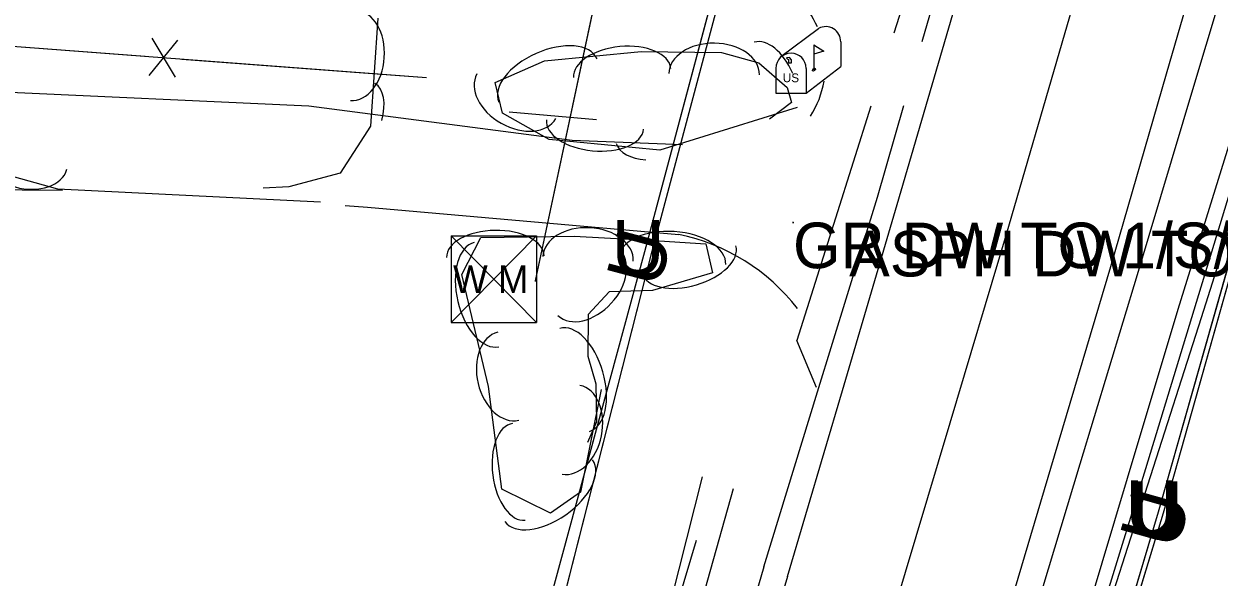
# Model space of a CAD drawing. Extents: x 954793 to 988390, y 1867850 to 1924428.
# Drawn here: x 961177.2 to 961308.1, y 1906549.5 to 1906610.1 of the extents above; entities that cross this region are included whole.
import ezdxf

# ---------------------------------------------------------------- set-up
doc = ezdxf.new("R2010")
doc.units = 0
for name, color, linetype in [('Default', 7, 'Continuous'), ('S_DITCHLINE', 7, 'Continuous'), ('S_DRIVEWAY', 7, 'Continuous'), ('S_EDGE_PAVEMENT', 7, 'Continuous'), ('S_FENCE', 7, 'Continuous'), ('S_FIBER_OPTIC_CABLE', 7, 'Continuous'), ('S_MAILBOX', 7, 'Continuous'), ('S_MSC_PT_SYM', 7, 'Continuous'), ('S_PAVEMENT_CROWN', 7, 'Continuous'), ('S_SHOULDER', 7, 'Continuous'), ('S_STREAM', 7, 'Continuous'), ('S_SURVEY_TEXT_ANNOT', 7, 'Continuous'), ('S_TREE', 7, 'Continuous'), ('S_UNDERGROUND_CABLE', 7, 'Continuous'), ('S_UTL_PT_SYM', 7, 'Continuous'), ('S_WATER_UTILITIES', 7, 'Continuous')]:
    doc.layers.add(name, color=color, linetype=linetype)

msp = doc.modelspace()

# ---------------------------------------------------------------- linework, layer by layer
at = {"layer": 'S_DITCHLINE'}
for points in [[(961281.36, 1906504.67), (961286.92, 1906523.21), (961292.47, 1906541.76), (961298.03, 1906560.31), (961303.59, 1906578.85), (961308.97, 1906596.26), (961314.35, 1906613.67), (961319.73, 1906631.07), (961325.12, 1906648.48), (961330.22, 1906665.83), (961335.33, 1906683.19), (961340.43, 1906700.54), (961345.54, 1906717.9), (961348.74, 1906734.13), (961351.94, 1906750.37), (961355.14, 1906766.6), (961358.34, 1906782.84), (961361.82, 1906806.99), (961365.31, 1906831.14), (961367.48, 1906844.45), (961369.65, 1906857.75), (961371.81, 1906871.05), (961373.98, 1906884.36), (961378.38, 1906886.56)], [(961282.64, 1906504.52), (961288.51, 1906522.87), (961294.39, 1906541.22), (961300.26, 1906559.57), (961306.13, 1906577.92), (961311.67, 1906595.41), (961317.2, 1906612.89), (961322.74, 1906630.37), (961328.27, 1906647.86), (961333.11, 1906665.38), (961337.96, 1906682.91), (961342.8, 1906700.43), (961347.64, 1906717.96), (961351.32, 1906734.05), (961354.99, 1906750.15), (961358.67, 1906766.25), (961362.35, 1906782.35), (961365.3, 1906806.52), (961368.26, 1906830.68), (961371.46, 1906851.53), (961374.67, 1906872.38)], [(961220.79, 1906448.63), (961225.92, 1906466.47), (961231.04, 1906484.31), (961236.17, 1906502.15), (961241.29, 1906519.99), (961246.4, 1906540.22), (961251.51, 1906560.45)], [(961222.13, 1906448.62), (961227.51, 1906466.25), (961232.88, 1906483.88), (961238.26, 1906501.51), (961243.64, 1906519.13), (961249.27, 1906539.15), (961254.9, 1906559.16)]]:
    msp.add_lwpolyline(points, dxfattribs=at)
at = {"layer": 'S_DRIVEWAY'}
for points in [[(961278.77, 1906629.04), (961274.53, 1906615.64), (961272.46, 1906609.07)], [(961249.3, 1906596.84), (961237.24, 1906597.32), (961208.39, 1906601.1), (961173.28, 1906602.68), (961146.27, 1906602.71), (961138.49, 1906603.17)], [(961269.93, 1906601.07), (961266.06, 1906588.82), (961261.82, 1906575.41)], [(961141.93, 1906588.1), (961163.73, 1906592.02), (961181.4, 1906591.86)], [(961212.38, 1906590.19), (961214.81, 1906590.01), (961248.89, 1906587.03)], [(961263.99, 1906570.24), (961261.82, 1906575.41)]]:
    msp.add_lwpolyline(points, dxfattribs=at)
for centre, major_axis, ratio, start_param, end_param in [((961254.62, 1906605.58), (-0.07, 10.35), 0.998866, 5.12227, 5.484198), ((961254.62, 1906605.58), (-0.07, 10.35), 0.998866, 4.136681, 4.533449), ((961244.25, 1906565.09), (-16.71, 14.97), 0.999649, 4.536311, 5.234086)]:
    msp.add_ellipse(centre, major_axis=major_axis, ratio=ratio, start_param=start_param, end_param=end_param, dxfattribs=at)
at = {"layer": 'S_EDGE_PAVEMENT'}
for points in [[(961260.82, 1906549.54), (961266.81, 1906569.92), (961272.8, 1906590.3), (961278.91, 1906611.17), (961285.01, 1906632.04), (961290.97, 1906653.41), (961296.93, 1906674.79), (961302.13, 1906694.47), (961307.33, 1906714.15), (961311.92, 1906734.12), (961316.51, 1906754.09), (961320.15, 1906774.24), (961323.79, 1906794.39), (961326.05, 1906811.77), (961328.31, 1906829.15), (961329.62, 1906844.79), (961330.93, 1906860.42), (961331.31, 1906876.09), (961331.42, 1906880.69)], [(961283.86, 1906541.96), (961290.03, 1906562.74), (961296.2, 1906583.52), (961302.31, 1906604.64), (961308.42, 1906625.77), (961314.44, 1906646.9), (961320.46, 1906668.02), (961325.86, 1906688.27), (961331.25, 1906708.51), (961336.02, 1906729.15), (961340.8, 1906749.78), (961344.46, 1906769.29), (961347.73, 1906786.69)], [(961260.82, 1906549.54), (961254.71, 1906529.11), (961248.6, 1906508.69)]]:
    msp.add_lwpolyline(points, dxfattribs=at)
at = {"layer": 'S_FENCE'}
for p, q in [((961191.2, 1906608.55), (961193.75, 1906604.25)), ((961190.89, 1906604.46), (961194.06, 1906608.33))]:
    msp.add_line(p, q, dxfattribs=at)
for points in [[(961170.56, 1906608.06), (961190.48, 1906606.55)], [(961170.56, 1906608.06), (961221.27, 1906604.22)], [(961194.47, 1906606.24), (961214.39, 1906604.74)], [(961214.39, 1906604.74), (961221.27, 1906604.22)], [(961230.32, 1906600.47), (961239.89, 1906599.62)]]:
    msp.add_lwpolyline(points, dxfattribs=at)
at = {"layer": 'S_FIBER_OPTIC_CABLE'}
for p, q in [((961245.94, 1906585.05), (961263.31, 1906650.29)), ((961231.67, 1906528.87), (961245.94, 1906585.05))]:
    msp.add_line(p, q, dxfattribs=at)
msp.add_lwpolyline([(961285.83, 1906512.94), (961239.76, 1906525.04), (961231.67, 1906528.87), (961245.94, 1906585.05), (961263.31, 1906650.29), (961274.95, 1906713.95), (961277.65, 1906742.92), (961276.99, 1906766.38), (961281.46, 1906820.82), (961281.51, 1906820.94), (961290.68, 1906871.65), (961288.29, 1906928.98), (961277.09, 1906978.27), (961271.41, 1906999.5), (961270.57, 1907011.18), (961252, 1907085.72), (961241.69, 1907119.93), (961193.03, 1907298.85), (961178.12, 1907348.06), (961184.61, 1907353.61)], dxfattribs=at)
msp.add_lwpolyline([(961285.83, 1906512.94), (961239.76, 1906525.04), (961231.67, 1906528.87), (961245.94, 1906585.05), (961263.31, 1906650.29), (961274.95, 1906713.95), (961277.65, 1906742.92), (961276.99, 1906766.38), (961281.46, 1906820.82), (961281.51, 1906820.94), (961290.68, 1906871.65), (961288.29, 1906928.98), (961277.09, 1906978.27), (961271.41, 1906999.5), (961270.57, 1907011.18), (961252, 1907085.72), (961241.69, 1907119.93), (961193.03, 1907298.85), (961178.12, 1907348.06), (961184.61, 1907353.61)], dxfattribs=at)
at = {"layer": 'S_MAILBOX'}
for p, q in [((961260.08, 1906606.51), (961264.21, 1906609.61)), ((961263.7, 1906607.79), (961263.7, 1906605.08)), ((961266.65, 1906608.14), (961266.65, 1906605.43)), ((961259.53, 1906605.23), (961259.53, 1906602.52)), ((961262.85, 1906602.52), (961266.65, 1906605.43)), ((961262.85, 1906605.23), (961262.85, 1906602.52)), ((961259.53, 1906602.52), (961262.85, 1906602.52))]:
    msp.add_line(p, q, dxfattribs=at)
for points in [[(961263.7, 1906607.79), (961264.8, 1906607.13), (961263.7, 1906606.78)], [(961260.71, 1906606.35), (961260.93, 1906606.21), (961260.93, 1906605.82), (961261.24, 1906605.82), (961261.24, 1906606.18), (961261.04, 1906606.43), (961260.71, 1906606.38)]]:
    msp.add_lwpolyline(points, dxfattribs=at)
for centre, end in [((961264.98, 1906608.14), 117.5718), ((961261.19, 1906605.23), 180)]:
    msp.add_arc(centre, 1.66, 0, end, dxfattribs=at)
msp.add_ellipse((961263.7, 1906605.08), major_axis=(0.145, 0.132), ratio=0.564646, dxfattribs=at)
at = {"layer": 'S_MSC_PT_SYM'}
for points in [[(961261.41, 1906588.32), (961261.41, 1906588.37), (961261.41, 1906588.32), (961261.36, 1906588.32), (961261.41, 1906588.32), (961261.41, 1906588.27), (961261.41, 1906588.32), (961261.46, 1906588.32)], [(961261.41, 1906588.32), (961261.41, 1906588.37), (961261.41, 1906588.32), (961261.36, 1906588.32), (961261.41, 1906588.32), (961261.41, 1906588.27), (961261.41, 1906588.32), (961261.46, 1906588.32)], [(961267.55, 1906587.42), (961267.55, 1906587.47), (961267.55, 1906587.42), (961267.5, 1906587.42), (961267.55, 1906587.42), (961267.55, 1906587.37), (961267.55, 1906587.42), (961267.6, 1906587.42)], [(961267.55, 1906587.42), (961267.55, 1906587.47), (961267.55, 1906587.42), (961267.5, 1906587.42), (961267.55, 1906587.42), (961267.55, 1906587.37), (961267.55, 1906587.42), (961267.6, 1906587.42)]]:
    msp.add_lwpolyline(points, close=True, dxfattribs=at)
for points in [[(961261.41, 1906588.32), (961261.41, 1906588.37), (961261.41, 1906588.32), (961261.36, 1906588.32), (961261.41, 1906588.32), (961261.41, 1906588.27), (961261.41, 1906588.32), (961261.46, 1906588.32)], [(961267.55, 1906587.42), (961267.55, 1906587.47), (961267.55, 1906587.42), (961267.5, 1906587.42), (961267.55, 1906587.42), (961267.55, 1906587.37), (961267.55, 1906587.42), (961267.6, 1906587.42)]]:
    msp.add_lwpolyline(points, dxfattribs=at)
at = {"layer": 'S_PAVEMENT_CROWN'}
msp.add_lwpolyline([(961272.44, 1906545.73), (961278.62, 1906566.39), (961284.8, 1906587.04), (961290.89, 1906608.02), (961296.98, 1906628.99), (961302.92, 1906649.89), (961308.86, 1906670.78), (961314.24, 1906691.33), (961319.62, 1906711.88), (961324.26, 1906732.19), (961328.89, 1906752.5), (961332.44, 1906772.12), (961336, 1906791.75), (961338.33, 1906809.48), (961340.65, 1906827.21), (961341.99, 1906843.07), (961343.32, 1906858.94), (961344.01, 1906875.13), (961344.7, 1906891.33)], dxfattribs=at)
at = {"layer": 'S_SHOULDER'}
for points in [[(961275.56, 1906608.18), (961276.64, 1906611.94), (961282.62, 1906632.76), (961288.58, 1906654.15), (961294.53, 1906675.54), (961299.76, 1906695.18), (961305, 1906714.81), (961309.53, 1906734.72), (961314.06, 1906754.62), (961317.88, 1906774.65), (961321.7, 1906794.68), (961324.05, 1906812.09), (961326.4, 1906829.49), (961327.64, 1906845.01), (961328.88, 1906860.53), (961329.23, 1906876.15), (961329.34, 1906881.19)], [(961276.43, 1906506.71), (961281.52, 1906523.93), (961286.61, 1906541.15), (961292.87, 1906561.89), (961299.14, 1906582.63), (961305.42, 1906603.65), (961311.71, 1906624.68), (961317.62, 1906645.89), (961323.53, 1906667.1), (961328.76, 1906687.47), (961333.98, 1906707.84), (961338.8, 1906728.39), (961343.61, 1906748.95), (961347.45, 1906768.64), (961350.81, 1906785.91)], [(961258.21, 1906550.57), (961264.1, 1906569.78), (961270.65, 1906591.11), (961273.54, 1906601.17)], [(961258.21, 1906550.57), (961252.21, 1906530.03), (961246.2, 1906509.49)]]:
    msp.add_lwpolyline(points, dxfattribs=at)
at = {"layer": 'S_STREAM'}
for points in [[(961282.71, 1906505.07), (961300.05, 1906561.36), (961317.86, 1906619.93), (961321.56, 1906631.69)], [(961250.81, 1906553.46), (961231.94, 1906490.14), (961223.43, 1906464.06)]]:
    msp.add_lwpolyline(points, dxfattribs=at)
at = {"layer": 'S_TREE'}
for points in [[(961209.67, 1906590.57), (961180.91, 1906591.97), (961158.64, 1906598.19), (961142.73, 1906605.51), (961134.65, 1906611.32)], [(961215.93, 1906610.72), (961215.15, 1906598.9), (961211.83, 1906593.74), (961206.2, 1906592.23), (961203.4, 1906592.1)], [(961261.86, 1906600.93), (961246.82, 1906596.26), (961234.7, 1906597.42), (961229.58, 1906600.31), (961228.78, 1906603.66), (961234.21, 1906606.06), (961244.8, 1906607.06), (961253.57, 1906606.96), (961257.68, 1906605.85), (961260.76, 1906603.14), (961261.23, 1906601.48), (961258.85, 1906599.67)], [(961240.42, 1906570.01), (961238.15, 1906558.79), (961234.85, 1906556.46), (961229.51, 1906559.1), (961228.05, 1906570.37), (961225.15, 1906582.65), (961227.23, 1906586.67), (961237.44, 1906586.83), (961246.76, 1906586.34), (961251.88, 1906586), (961252.6, 1906582.82), (961246.03, 1906580.88), (961241.28, 1906580.72), (961238.99, 1906578.23), (961238.94, 1906573.69), (961239.83, 1906570.64), (961239.9, 1906566.49), (961238.92, 1906564.21)]]:
    msp.add_lwpolyline(points, dxfattribs=at)
for centre, major_axis, ratio, start_param, end_param in [((961213.27, 1906606.63), (0.33, 4.94), 0.685311, 3.141593, 6.283185), ((961234.58, 1906603.91), (-5.37, -2.38), 0.55008, 3.141593, 6.283185), ((961242.71, 1906604.73), (-5.32, -0.5), 0.540699, 3.141593, 6.283185), ((961252.77, 1906604.59), (-4.96, 0.06), 0.685311, 3.141593, 6.283185), ((961258.75, 1906602.44), (-1.58, 5.65), 0.55008, 4.961352, 6.283185), ((961231.12, 1906602.18), (4.32, -2.44), 0.685311, 3.141593, 6.283185), ((961212.46, 1906598.64), (3.17, 4.94), 0.55008, 5.220638, 6.283185), ((961239.72, 1906599.07), (5.32, -0.51), 0.540699, 3.141593, 6.283185), ((961177.13, 1906595.5), (4.77, -1.33), 0.685311, 3.141593, 6.283185), ((961247.66, 1906598.74), (5.6, 1.74), 0.55008, 3.141593, 4.116161), ((961238.97, 1906584.36), (-4.95, 0.26), 0.685311, 3.141593, 6.283185), ((961228.82, 1906584.58), (-5.35, -0.08), 0.540699, 3.141593, 6.283185), ((961248.19, 1906584.12), (-5.85, 0.4), 0.55008, 3.141593, 6.283185), ((961227.85, 1906580.43), (1.35, -5.71), 0.55008, 3.141593, 6.283185), ((961239.01, 1906581.77), (3.35, 3.65), 0.685311, 3.141593, 6.283185), ((961250.02, 1906584.27), (5.13, 1.51), 0.540699, 3.141593, 6.283185), ((961237.49, 1906571.08), (-1.63, 5.64), 0.55008, 3.141593, 6.283185), ((961230.23, 1906571.48), (1.14, -4.82), 0.685311, 3.141593, 6.283185), ((961237.1, 1906565.62), (0.98, 4.86), 0.685311, 3.141593, 6.283185), ((961231.4, 1906561), (0.69, -5.3), 0.540699, 3.141593, 6.283185), ((961234.67, 1906558.93), (4.8, 3.37), 0.55008, 3.141593, 6.283185)]:
    msp.add_ellipse(centre, major_axis=major_axis, ratio=ratio, start_param=start_param, end_param=end_param, dxfattribs=at)
at = {"layer": 'S_UNDERGROUND_CABLE'}
for p, q in [((961245.18, 1906585.14), (961262.51, 1906650.28)), ((961301.44, 1906556.6), (961319.94, 1906621.93)), ((961301.96, 1906556.5), (961320.37, 1906621.87)), ((961229.29, 1906526.62), (961245.18, 1906585.14)), ((961286.84, 1906506.75), (961301.96, 1906556.5)), ((961287.95, 1906511.37), (961301.44, 1906556.6))]:
    msp.add_line(p, q, dxfattribs=at)
for points in [[(961219.85, 1906506.18), (961224.66, 1906512.65), (961229.29, 1906526.62), (961245.18, 1906585.14), (961262.51, 1906650.28), (961274.33, 1906713.58), (961277.08, 1906742.86), (961276.18, 1906766.43), (961280.48, 1906820.72), (961289.88, 1906871.79), (961287.25, 1906929.1), (961276.23, 1906978.14), (961270.69, 1906999.66), (961269.7, 1907011.39), (961250.98, 1907085.77), (961240.81, 1907120.21), (961192.22, 1907298.69), (961177.3, 1907348.84), (961184.15, 1907354.03)], [(961219.85, 1906506.18), (961224.66, 1906512.65), (961229.29, 1906526.62), (961245.18, 1906585.14), (961262.51, 1906650.28), (961274.33, 1906713.58), (961277.08, 1906742.86), (961276.18, 1906766.43), (961280.48, 1906820.72), (961289.88, 1906871.79), (961287.25, 1906929.1), (961276.23, 1906978.14), (961270.69, 1906999.66), (961269.7, 1907011.39), (961250.98, 1907085.77), (961240.81, 1907120.21), (961192.22, 1907298.69), (961177.3, 1907348.84), (961184.15, 1907354.03)], [(961235.98, 1906272.67), (961234.52, 1906289.79), (961237.41, 1906336.16), (961259.1, 1906413.43), (961274.29, 1906465.46), (961286.75, 1906507.83), (961287.95, 1906511.37), (961301.44, 1906556.6), (961319.94, 1906621.93), (961339.42, 1906688.33), (961359.47, 1906772.42), (961371.71, 1906890.76)], [(961235.98, 1906272.67), (961234.52, 1906289.79), (961237.41, 1906336.16), (961259.1, 1906413.43), (961274.29, 1906465.46), (961286.75, 1906507.83), (961287.95, 1906511.37), (961301.44, 1906556.6), (961319.94, 1906621.93), (961339.42, 1906688.33), (961359.47, 1906772.42), (961371.71, 1906890.76)], [(961237.16, 1906272.63), (961234.85, 1906289.95), (961237.93, 1906335.88), (961259.63, 1906413.4), (961275.07, 1906465.07), (961286.84, 1906506.75), (961301.96, 1906556.5), (961320.37, 1906621.87), (961339.85, 1906688.2), (961360.13, 1906772.32), (961371.94, 1906890.71)], [(961237.16, 1906272.63), (961234.85, 1906289.95), (961237.93, 1906335.88), (961259.63, 1906413.4), (961275.07, 1906465.07), (961286.84, 1906506.75), (961301.96, 1906556.5), (961320.37, 1906621.87), (961339.85, 1906688.2), (961360.13, 1906772.32), (961371.94, 1906890.71)]]:
    msp.add_lwpolyline(points, dxfattribs=at)
at = {"layer": 'S_UTL_PT_SYM'}
for points in [[(961245.94, 1906585.05), (961245.89, 1906585.06), (961245.94, 1906585.05), (961245.93, 1906585), (961245.94, 1906585.05), (961245.99, 1906585.04), (961245.94, 1906585.05), (961245.95, 1906585.1)], [(961245.94, 1906585.05), (961245.89, 1906585.06), (961245.94, 1906585.05), (961245.93, 1906585), (961245.94, 1906585.05), (961245.99, 1906585.04), (961245.94, 1906585.05), (961245.95, 1906585.1)], [(961233.21, 1906581.92), (961233.16, 1906581.93), (961233.21, 1906581.92), (961233.2, 1906581.87), (961233.21, 1906581.92), (961233.26, 1906581.91), (961233.21, 1906581.92), (961233.22, 1906581.97)], [(961233.21, 1906581.92), (961233.16, 1906581.93), (961233.21, 1906581.92), (961233.2, 1906581.87), (961233.21, 1906581.92), (961233.26, 1906581.91), (961233.21, 1906581.92), (961233.22, 1906581.97)]]:
    msp.add_lwpolyline(points, close=True, dxfattribs=at)
for points in [[(961245.94, 1906585.05), (961245.94, 1906585.1), (961245.94, 1906585.05), (961245.89, 1906585.05), (961245.94, 1906585.05), (961245.94, 1906585), (961245.94, 1906585.05), (961245.99, 1906585.05)], [(961233.21, 1906581.92), (961233.21, 1906581.97), (961233.21, 1906581.92), (961233.16, 1906581.92), (961233.21, 1906581.92), (961233.21, 1906581.87), (961233.21, 1906581.92), (961233.26, 1906581.92)]]:
    msp.add_lwpolyline(points, dxfattribs=at)
at = {"layer": 'S_WATER_UTILITIES'}
for p, q in [((961233.21, 1906581.92), (961239.88, 1906613.32)), ((961223.99, 1906586.86), (961233.33, 1906586.86)), ((961223.99, 1906586.86), (961223.99, 1906577.36)), ((961223.99, 1906586.86), (961233.33, 1906577.36)), ((961233.33, 1906586.86), (961223.99, 1906577.36)), ((961233.33, 1906586.86), (961233.33, 1906577.36)), ((961223.99, 1906577.36), (961233.33, 1906577.36))]:
    msp.add_line(p, q, dxfattribs=at)
msp.add_lwpolyline([(961233.21, 1906581.92), (961239.88, 1906613.32), (961245.65, 1906637.53), (961246.05, 1906642.65), (961243.1, 1906645.82), (961246.26, 1906663.24), (961260.29, 1906722.58), (961260.27, 1906721.68), (961272.47, 1906777.72), (961274.65, 1906810.79), (961278.54, 1906880.67), (961277.46, 1906916.71), (961272.44, 1906998.38), (961266.13, 1907021.45), (961255.35, 1907062.93), (961239.3, 1907122.22), (961178.98, 1907279.14), (961156.47, 1907362.93), (961139.98, 1907424.6), (961123.39, 1907478.88), (961104.6, 1907524.33), (961089.95, 1907561.75), (961070.69, 1907621.77), (961035.76, 1907704.59)], dxfattribs=at)
msp.add_lwpolyline([(961233.21, 1906581.92), (961239.88, 1906613.32), (961245.65, 1906637.53), (961246.05, 1906642.65), (961243.1, 1906645.82), (961246.26, 1906663.24), (961260.29, 1906722.58), (961260.27, 1906721.68), (961272.47, 1906777.72), (961274.65, 1906810.79), (961278.54, 1906880.67), (961277.46, 1906916.71), (961272.44, 1906998.38), (961266.13, 1907021.45), (961255.35, 1907062.93), (961239.3, 1907122.22), (961178.98, 1907279.14), (961156.47, 1907362.93), (961139.98, 1907424.6), (961123.39, 1907478.88), (961104.6, 1907524.33), (961089.95, 1907561.75), (961070.69, 1907621.77), (961035.76, 1907704.59)], dxfattribs=at)

# ---------------------------------------------------------------- texts
at = {"layer": 'Default'}
for rotation, p in [(360, (961241.55, 1906582.59)), (75.1034, (961246.71, 1906580.98)), (74.1915, (961302.9, 1906552.42)), (74.2697, (961303.42, 1906552.32)), (360, (961297.81, 1906554.06)), (360, (961298.33, 1906553.95))]:
    msp.add_text('U', height=6, rotation=rotation, dxfattribs=at).set_placement(p)
at = {"layer": 'S_MAILBOX'}
msp.add_text('US', height=0.96, rotation=360, dxfattribs=at).set_placement((961260.29, 1906603.71))
at = {"layer": 'S_SURVEY_TEXT_ANNOT'}
for s, p in [('GR DW TO 1/S/FRAME NO CUS', (961261.41, 1906583.32)), ('ASPH DW TO 1SF', (961267.55, 1906582.42))]:
    msp.add_text(s, height=5, dxfattribs=at).set_placement(p)
at = {"layer": 'S_WATER_UTILITIES'}
msp.add_text('W M', height=3, rotation=360, dxfattribs=at).set_placement((961224.19, 1906580.62))

doc.saveas('drawing.dxf')
